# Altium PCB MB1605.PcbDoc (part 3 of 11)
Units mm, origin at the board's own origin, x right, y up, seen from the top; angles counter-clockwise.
Board outline 100 x 79.6 mm, 6 copper layers (Top Layer, Signal Layer 1, Signal Layer 2, Signal Layer 3, Signal Layer 4, Bottom Layer), stack 1.549 mm thick; 644 components, 529 nets, 2853 pads, 1462 vias.
Unrouted connection lines stored in the file: 2.
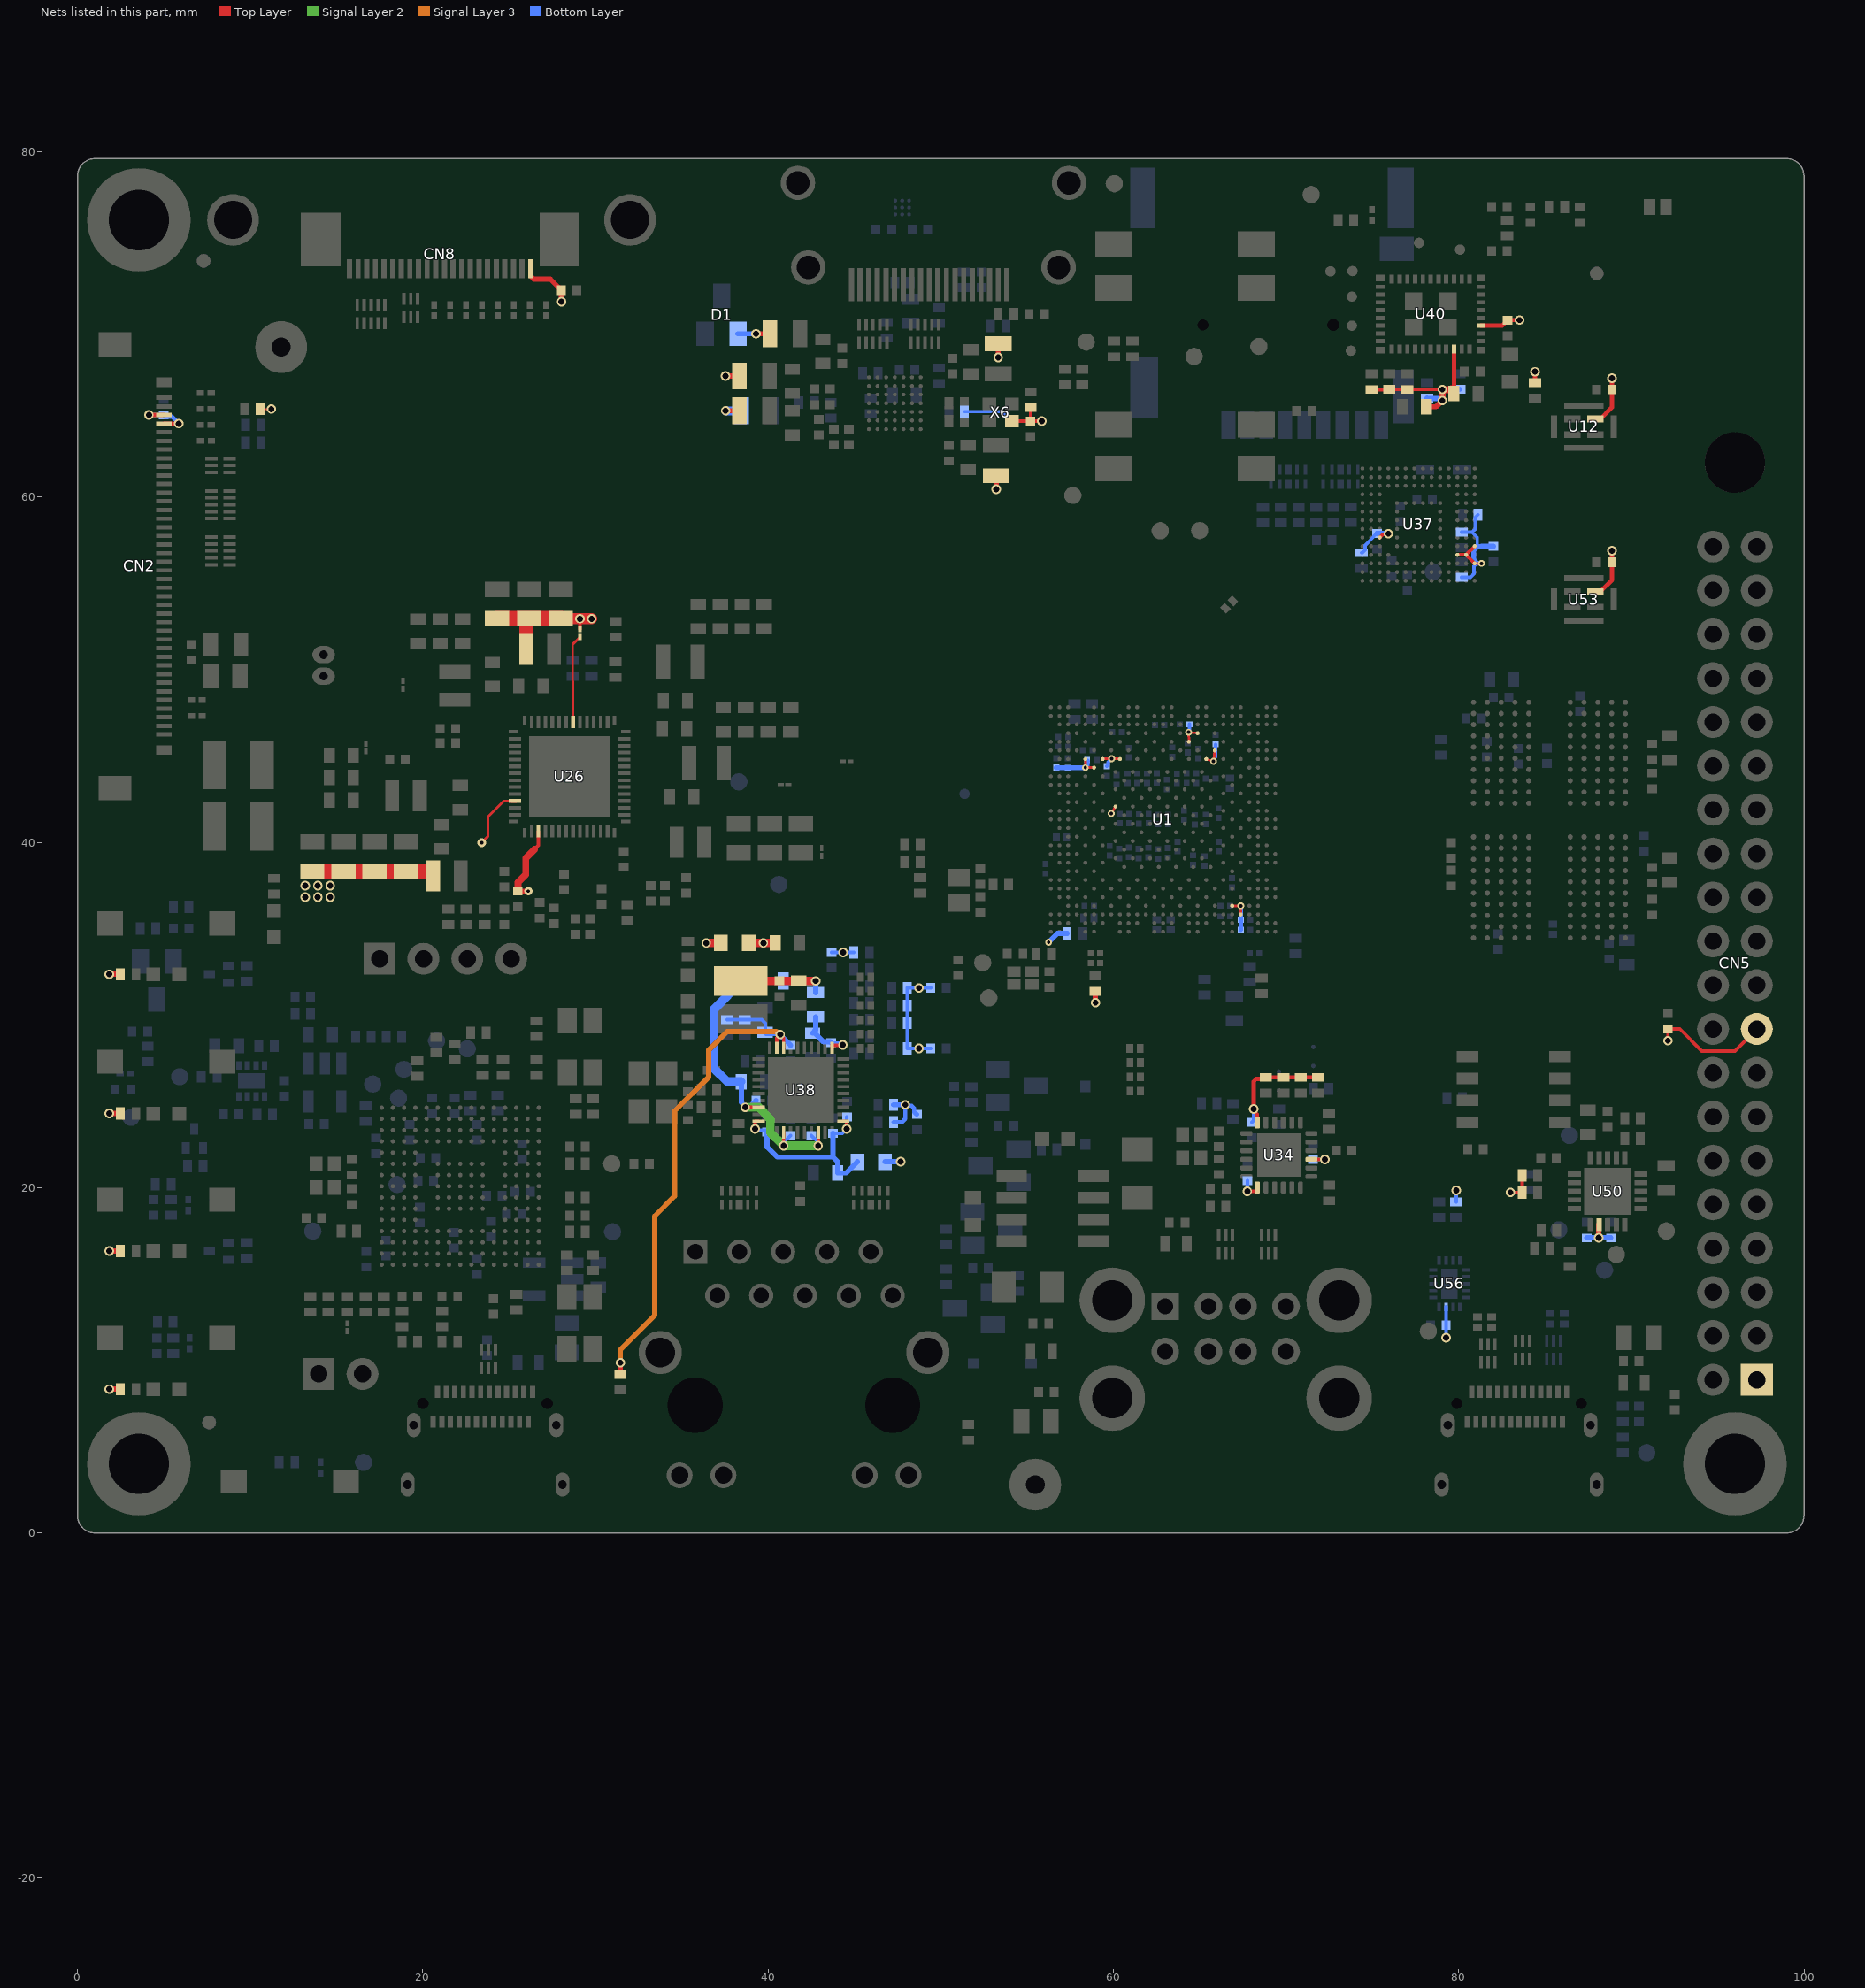
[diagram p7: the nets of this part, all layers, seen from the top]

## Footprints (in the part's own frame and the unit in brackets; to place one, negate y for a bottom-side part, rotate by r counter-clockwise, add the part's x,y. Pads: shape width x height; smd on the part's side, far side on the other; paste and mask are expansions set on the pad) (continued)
MIC_HCLGA_3X4X1_4LD [mm] "MCD-01715"
  rect 0.4x0.95 smd paste+0 mask+0.05: 1(0.45,-1.175) 2(0.45,0.175) 3(-0.45,0.175) 4(-0.45,-1.175)
  rect 0.35x2.3 smd paste+0 mask+0.05: 5(-1.225,-0.5) 5(1.225,-0.5)
  rect 1.3x0.35 smd paste+0 mask+0.05: 5(0,1.225) 5(0,-2.225)
  silkscreen extent -1.55,-2.55 1.55,1.55, body extent -1.45,-2.45 1.45,1.45, height 1.03
MIRE_PLACE_SMD_0P8MM [mm]
  round 0.8 smd paste-10 mask+0.2: 1(0,0)
  Top Layer keep-out circle w0.01: c0,0 r0.804
MOD_WLAN-BT_MURATA_LBEE5KL1YN-814 [mm]
  rect 0.25x0.5 smd mask+0.05: 1(-2.25,-2.025) 2(-1.8,-2.025) 3(-1.35,-2.025) 4(-0.9,-2.025) 5(-0.45,-2.025) 6(0,-2.025) 7(0.45,-2.025) 8(0.9,-2.025) 9(1.35,-2.025) 10(1.8,-2.025) 11(2.25,-2.025) 22(2.25,2.025) 23(1.8,2.025) 24(1.35,2.025) 25(0.9,2.025) 26(0.45,2.025) 27(0,2.025) 28(-0.45,2.025) 29(-0.9,2.025) 30(-1.35,2.025) 31(-1.8,2.025) 32(-2.25,2.025)
  rect 0.5x0.375 smd mask+0.05: 12(2.925,-2.087) 21(2.925,2.087) 33(-2.925,2.087) 42(-2.925,-2.087)
  rect 0.5x0.25 smd mask+0.05: 13(2.925,-1.575) 14(2.925,-1.125) 15(2.925,-0.675) 16(2.925,-0.225) 17(2.925,0.225) 18(2.925,0.675) 19(2.925,1.125) 20(2.925,1.575) 34(-2.925,1.575) 35(-2.925,1.125) 36(-2.925,0.675) 37(-2.925,0.225) 38(-2.925,-0.225) 39(-2.925,-0.675) 40(-2.925,-1.125) 41(-2.925,-1.575)
  rect 1x1 smd mask+0.05: 43(-1,-0.75) 44(1,-0.75) 45(-1,0.75) 46(1,0.75)
  silkscreen extent -3.57,-2.68 3.57,2.68, body extent -3.57,-2.68 3.57,2.68, height 1.11
MOS_SC89-3L [mm] "MCD-02221"
  rect 0.46x0.65 smd mask+0.05: 1(-0.5,-0.55) 2(0.5,-0.55) 3(0,0.55)
  silkscreen extent -0.85,-0.48 0.85,0.48, body extent -0.85,-0.85 0.85,0.85, height 0.85
MOS_SOT23 [mm]
  rect 1x1.4 smd mask+0.05: 1(-0.95,-1.1) 2(0.95,-1.1) 3(0,1.1)
  silkscreen extent -1.63,-0.82 1.63,0.82, body extent -1.56,-1.25 1.56,1.25, height 1.1
MOS_SOT23-5L [mm]
  rect 0.6x1.3 smd mask+0.05: 1(-0.95,-1.1) 2(0,-1.1) 3(0.95,-1.1) 4(0.95,1.1) 5(-0.95,1.1)
  silkscreen extent -1.6,-0.95 1.6,0.97, body extent -1.52,-1.25 1.52,1.25, height 1.45
PowerFLAT_5x6 [mm] "MCD-02152"
  rect 0.65x1.25 smd mask+0.05: 1(1.905,2.675) 2(0.635,2.675) 3(-0.635,2.675) 4(-1.905,2.675) 5(-1.905,-2.675) 6(-0.635,-2.675) 7(0.635,-2.675) 8(1.905,-2.675)
  Top Layer region: 0.2,-3.3 0.95,-3.3 0.95,-2.75 1.575,-2.75 1.575,-3.3 2.3,-3.3 2.3,-2.3 2.7,-2.3 2.7,-1.5 2.3,-1.5 2.3,0.15 2.7,0.15 2.7,0.975 2.3,0.975 2.3,1.15 0.2,1.15
  Top Layer region: -0.2,-3.3 -0.95,-3.3 -0.95,-2.75 -1.575,-2.75 -1.575,-3.3 -2.3,-3.3 -2.3,-2.3 -2.7,-2.3 -2.7,-1.5 -2.3,-1.5 -2.3,0.15 -2.7,0.15 -2.7,0.975 -2.3,0.975 -2.3,1.15 -0.2,1.15
  silkscreen extent -2.5,-3 2.5,3, body extent -2.6,-3.08 2.6,3.07, height 1
R0201_H0P23 [mm] "MCD-00702"
  rect 0.4x0.5 smd mask+0.05: 1(-0.3,0) 2(0.3,0)
  body extent -0.32,-0.17 0.32,0.17, height 0.26
R0402 [mm]
  rect 0.51x0.7 smd mask+0.05: 1(-0.45,0) 2(0.45,0)
  body extent -0.52,-0.3 0.52,0.3, height 0.4
R0603 [mm]
  rect 0.64x1 smd mask+0.05: 1(-0.7,0) 2(0.7,0)
  silkscreen extent -1.05,-0.58 1.05,0.58, body extent -0.9,-0.5 0.9,0.5, height 0.56
R0805 [mm]
  rect 0.85x1.3 smd mask+0.05: 1(-0.875,0) 2(0.875,0)
  silkscreen extent -0.33,-0.67 0.33,0.67, body extent -1.05,-0.68 1.05,0.68, height 0.65
Sheetbox_6L2S [mil] "Sheetbox 6 layers / 2 silkscreens"
  round 20 on Mech16: 1(813.5,208.05) 1(2736.63,208.05)
SOLDER-BRIDGE_R0603-0R [mil]
  round 10 smd paste-393.7: 1(-19.68,0) 2(23.62,0)
  Top Layer region: -47.24,-19.69 -47.24,19.68 -15.75,19.68 3.94,0 -15.75,-19.69 -47.24,-19.69
  Top Layer region: -5.91,19.68 13.78,0 -5.91,-19.69 47.24,-19.69 47.24,19.68 -5.91,19.68
  silkscreen extent -50,-23 50,23, body extent -36,-20 36,20, height 22
SWI_C&K_SDA02H1SBD_2POS [mm]
  rect 1.5x2.15 smd mask+0.05: 1(-1.27,-4.125) 2(1.27,-4.125) 3(1.27,4.125) 4(-1.27,4.125)
  silkscreen extent -3.55,-3.75 3.55,3.75, body extent -3.53,-4.65 3.53,4.65, height 5.45
SWI_WE_4341x10258x6 [mm]
  rect 1.5x1.4 smd: 1(-3.25,0) 2(3.25,0)
  silkscreen extent -3,-1.95 3,1.95, body extent -3.65,-1.95 3.65,1.95, height 2.5
SWI_WE_434121025816 [mm] "MCD-03492"
  rect 1.5x1.4 smd: 1(-3.25,0) 2(3.25,0)
  silkscreen extent -3,-1.95 3,1.95, body extent -3.65,-1.95 3.65,1.95, height 2.51
TP_PTH-1P02MM_TEST-TERMINAL_RS_101-2391_BLACK [mm] "MCD-00713"
  round 3 hole 1.1 mask+0.05: 1(0,0)
  silkscreen extent -1.62,-1.63 1.62,1.63, body extent -1.24,-1.25 1.25,1.25, height 4.85
TP_SMD_0-6MM [mm]
  round 0.6 smd paste-10 mask+0.05: 1(0,0)
  silkscreen extent -0.5,-0.5 0.5,0.5
TP_SMD_1MM [mm]
  round 1 smd paste-10 mask+0.05: 1(0,0)
  silkscreen extent -0.7,-0.7 0.7,0.7

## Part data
B1 B2 B3: library part MCD-03492, "Switch tactile, SPST-NO, 50mA, 12V, 6x3.8mm", Manufacturer="WURTH ELEKTRONIC", Manufacturer_Part_Number=434121025816, Package=6x3.8mm
B4 B5: library part MCD-03491, "Switch tactile, SPST-NO, 50mA, 12V, 6x3.8mm", Manufacturer="WURTH ELEKTRONIC", Manufacturer_Part_Number=434111025826, Package=6x3.8mm
C1 C90 C92 C119: library part MCD-00674, "Capacitor, MLCC, 6.8pF, 50V, NPO, +-0.25pF, 0402, T=0.5mm", Alternate_Manufacturer=N/A, Manufacturer=YAGEO, Manufacturer_Part_Number=CC0402CRNPO9BN6R8, Package=0402
C2 C3 C10 C11: library part MCD-01341, "Capacitor, MLCC, 10uF, 6V3, X5R, 20%, 0603, T=0,8mm", Alternate_Manufacturer=MURATA, Alternate_Manufacturer_Part_Number=GRM188R60J106ME84D, Manufacturer_Part_Number=GRM188R60J106ME47D, Package=0603
C4 C5 C6 C7 C8 C12 C13 C14 C15 C16 C17 C18 C19 C20 C21 C31 C101 C102 C105 C106 C107 C108 C113 C122 C125 C139 C146 C149 C155 C177 C180 C181 C182 C227 C232 C233 C281 C282 C289 C290 C297 C298 C299 C303 C310 C311 C324 C325 C326 C327 C328 C329 C333 C334: library part MCD-00006, "Capacitor, MLCC, 100nF, 16V, X7R, +/-10%, 0402, T=0.5mm", Manufacturer=YAGEO, Manufacturer_Part_Number=CC0402KRX7R7BB104, Package=0402
C9 C89 C114 C115 C116 C118 C126 C127 C130 C161 C162: library part MCD-00006, "Capacitor, MLCC, 100nF, 16V, X7R, +/-10%, 0402, T=0.5mm", Alternate_Manufacturer=MURATA, Alternate_Manufacturer_Part_Number=GCM155R71C104KA55D, Manufacturer=YAGEO, Manufacturer_Part_Number=CC0402KRX7R7BB104, Package=0402
C22 C23 C24 C26 C27 C28 C34 C35 C36 C37 C41 C183 C200 C202: library part MCD-00100, "Capacitor, MLCC, 22uF, 6V3, X5R, +/-20%, 0603, T=0,8mm", Alternate_Manufacturer=N/A, Manufacturer=MURATA, Manufacturer_Part_Number=GRM188R60J226MEA0J, Package=0603
C25 C157 C158 C173 C219: library part MCD-02198, "Capacitor, MLCC, 10nF, 50V, X7R, +/-10%, 0402, T=0.5mm", Manufacturer=YAGEO, Manufacturer_Part_Number=CC0402KRX7R9BB103, Package=0402
C29 C30 C32 C38 C56 C184 C199: library part MCD-00099, "Capacitor, MLCC, 10uF, 10V, X5R, +/-10%, 0603, T=0,8mm", Alternate_Manufacturer=N/A, Manufacturer=MURATA, Manufacturer_Part_Number=GRM188R61A106KE69D, Package=0603
C33: library part MCD-00011, "Capacitor, MLCC, 10nF, 16V, X7R, 10%, 0402, T=0.5mm", Manufacturer=YAGEO, Manufacturer_Part_Number=CC0402KRX7R7BB103, Package=C0402
C39 C43 C188 C213 C216: library part MCD-00095, "Capacitor, MLCC, 1uF, 25V, X5R, +/-10%, 0402, T=0.5mm", Manufacturer=MURATA, Manufacturer_Part_Number=GRM155R61E105KA12, Package=0402
C40: library part MCD-03140, "Capacitor, MLCC, 10uF, 6.3V, X5R, +/-20%, 0402, T=0.5mm", Manufacturer=MURATA, Manufacturer_Part_Number=GRM155R60J106ME05D, Package=0402
C42 C147: library part MCD-01796, "Capacitor, Tantalum, 100uF, 6V3, 40mR, +/-20%,  Type_B (3528 metric), T=1.9mm", Manufacturer=AVX, Manufacturer_Part_Number=TCJB107M006R0040, Package="3528 (metric)"
C44 C45 C46 C47 C48 C49 C50 C51 C52 C53 C54 C55 C57 C58 C59 C60 C62 C63 C64 C65 C66 C67 C68 C69 C70 C71 C72 C73 C74 C75 C76 C77 C82 C83: library part MCD-02377, "Capacitor, MLCC, 1uF, 6.3V, X5R, +/-20%, 0201, T=0,3mm", Manufacturer=MURATA, Manufacturer_Part_Number=GRM033R60J105MEA2, Package=0201
C61 C91 C179 C189 C190 C208 C209 C214 C215 C217 C335: library part MCD-01356, "Capacitor, MLCC, 4.7uF, 6V3, X5R, +/-20%, 0402, T=0.5mm", Manufacturer=MURATA, Manufacturer_Part_Number=GRM155R60J475ME47, Package=0402
C78 C79 C80 C96 C97 C98: library part MCD-00100, "Capacitor, MLCC, 22uF, 6V3, X5R, +/-20%, 0603, T=0.8mm", Manufacturer=MURATA, Manufacturer_Part_Number=GRM188R60J226MEA0J, Package=0603
C81 C86: library part MCD-01775, "Capacitor, MLCC, 3.3pF, 50V, NPO, +/-0.1pF, 0402, T=0.5mm", Manufacturer=YAGEO, Manufacturer_Part_Number=CC0402BRNPO9BN3R3, Package=0402
C84 C93: library part MCD-02352, "Capacitor, MLCC, 100nF, 10V, X5R, +/-10%, 0402, T=0,5mm", Manufacturer=YAGEO, Manufacturer_Part_Number=CC0402KRX5R6BB104, Package=0402
C85 C143: library part MCD-00204, "Capacitor, MLCC, 47uF, 10V, X5R, +/-20%, 0805, T=1.25mm", Manufacturer=MURATA, Manufacturer_Part_Number=GRM21BR61A476ME15K, Package=0805
C87 C103 C104 C109 C123 C137 C141 C152 C228 C229 C295 C296 C306 C309 C314 C317 C322 C323: library part MCD-00006, "Capacitor,100nF,16V,X7R,10%,0402", Alternate_Manufacturer=MURATA, Alternate_Manufacturer_Part_Number=GCM155R71C104KA55D, Manufacturer=YAGEO, Manufacturer_Part_Number=CC0402KRX7R7BB104, Package=0402
C88: library part MCD-01823, "Capacitor, MLCC, 2.2uF, 6V3, X5R,+/-10%, 0402, T=0.5mm", Alternate_Manufacturer=N/A, Manufacturer=MURATA, Manufacturer_Part_Number=GRM155R60J225KE95D, Package=0402
C94: library part MCD-01995, "Capacitor, MLCC, 22pF, 50V, C0G, +/-5%, 0402, T=0.5mm", Manufacturer=TDK, Manufacturer_Part_Number=C1005NP01H220J050BA, Package=0402
C95 C163 C212: library part MCD-00198, "Capacitor, MLCC, 1nF, 16V, X7R, +/-10%, 0402, T=0.5mm", Manufacturer=YAGEO, Manufacturer_Part_Number=CC0402KRX7R7BB102, Package=0402
C99: library part MCD-00011, "Capacitor, MLCC, 10nF, 16V, X7R, 10%, 0402, T=0.5mm", Alternate_Manufacturer=N/A, Manufacturer=YAGEO, Manufacturer_Part_Number=CC0402KRX7R7BB103, Package=0402
C100 C265 C266 C267: library part MCD-00697, "Capacitor, MLCC, 100nF,10V, X5R, +/-10%, 0201, T=0.3mm", Alternate_Manufacturer=N/A, Manufacturer=TDK, Manufacturer_Part_Number=C0603X5R1A104K030BC, Package=0201
C110 C159: library part MCD-02372, "Capacitor, MLCC, 2.2uF, 25V, X7R, +/-10%, 0805, T=1,25mm", Manufacturer=MURATA, Manufacturer_Part_Number=GRM21BR71E225KE11L, Package=0805
C111 C120 C280 C288 C302 C332: library part MCD-00100, "Capacitor,22uF,6V3,X5R,20%,0603", Manufacturer=MURATA, Manufacturer_Part_Number=GRM188R60J226MEA0J, Package=0603
C117 C128 C132 C145 C148 C160: library part MCD-02606, "Capacitor, MLCC, 2.2uF, 6.3V, X5R, +/-10%, 0402, T=0.5mm", Manufacturer=YAGEO, Manufacturer_Part_Number=CC0402KRX5R5BB225, Package=0402
C129 C165 C169: library part MCD-00099, "Capacitor, MLCC, 10uF, 10V, X5R, +/-10%, 0603, T=0.8mm", Manufacturer=MURATA, Manufacturer_Part_Number=GRM188R61A106KE69D, Package=0603
C131: library part MCD-00016, "Capacitor, MLCC, 20pF, 50V, NPO, +/- 5%, 0402, T=0.5mm", Manufacturer=YAGEO, Manufacturer_Part_Number=CC0402JRNPO9BN200, Package=0402
C133 C140: library part MCD-01374, "Capacitor, MLCC, 5.6pF, 50V, NPO, +/-0.1pF, 0402, T=0.5mm", Manufacturer=YAGEO, Manufacturer_Part_Number=CC0402BRNPO9BN5R6, Package=0402
C134 C218: library part MCD-01356, "Capacitor, MLCC, 4.7uF, 6V3, X5R, 20%, 0402, T=0,5mm", Alternate_Manufacturer=MURATA, Alternate_Manufacturer_Part_Number=GRM155R60J475ME87, Manufacturer_Part_Number=GRM155R60J475ME47, Package=0402
C135: library part MCD-00099, "Capacitor, MLCC, 10uF, 10V, X5R, 10%, 0603, T=0,8mm", Manufacturer=MURATA, Manufacturer_Part_Number=GRM188R61A106KE69D, Package=0603
C136: library part MCD-00012, "Capacitor, MLCC, 2.2uF, 10V, X5R, 10%, 0603, T=0,8mm", Alternate_Manufacturer=KEMET, Alternate_Manufacturer_Part_Number=C0603C225K8PACTU, Manufacturer=YAGEO, Manufacturer_Part_Number=CC0603KRX5R6BB225, Package=0603
C150 C226: library part MCD-00104, "Capacitor, MLCC, 220uF, 6V3, X5R, +/-20%, 1206, T=1.6mm", Manufacturer=MURATA, Manufacturer_Part_Number=GRM31CR60J227ME11, Package=1206
C151 C250 C252 C260: library part MCD-02377, "Capacitor, MLCC, 1uF, 6.3V, X5R, +/-20%, 0201, T=0,3mm", Alternate_Manufacturer=N/A, Manufacturer=MURATA, Manufacturer_Part_Number=GRM033R60J105MEA2, Package=0201
C156 C164: library part MCD-00205, "Capacitor, MLCC, 100pF, 50V, NPO, +/-5%, 0402, T=0.5mm", Manufacturer=YAGEO, Manufacturer_Part_Number=CC0402JRNPO9BN101, Package=0402
C166 C172: library part MCD-02355, "Capacitor, MLCC, 100nF, 25V, X7R, +/-10%, 0402, T=0.5mm", Manufacturer=WALSIN, Manufacturer_Part_Number=0402B104K250CT, Package=0402
C167 C174 C175 C176: library part MCD-00200, "Capacitor, MLCC, 12pF, 50V, NPO, 5%, 0402, T=0,5mm", Alternate_Manufacturer=N/A, Manufacturer=YAGEO, Manufacturer_Part_Number=CC0402JRNPO9BN120, Package=0402
C168 C171: library part MCD-00724, "Capacitor, MLCC, 470pF, 50V, NPO, +/-5%, 0402, T=0.5mm", Manufacturer=YAGEO, Manufacturer_Part_Number=CC0402JRNPO9BN471, Package=0402
C170: library part MCD-01099, "Capacitor, MLCC, 100nF, 50V, X7R, +/-10%, 0603, T=0.8mm", Manufacturer=YAGEO, Manufacturer_Part_Number=CC0603KRX7R9BB104, Package=0603
C185 C186 C187 C193 C194 C198 C203 C204 C206 C207: library part MCD-03139, "Capacitor, MLCC, 22uF, 10V, X5R, +/-20%, 0805, T=1,25mm", Manufacturer=MURATA, Manufacturer_Part_Number=GRM21BR61A226ME51L, Package=0805
C192 C195 C196 C197 C201 C205 C220 C234 C236 C237 C238 C239 C240 C244 C246 C248 C251 C253: library part MCD-01535, "Capacitor, MLCC,100nF, 10V, X7R, +/-10%, 0201, T=0.3mm", Alternate_Manufacturer=N/A, Manufacturer=MURATA, Manufacturer_Part_Number=GRM033R61A104KE15, Package=0201
C222 C223: library part MCD-00015, "Capacitor,10pF,50V,NPO,5%,0402", Manufacturer=YAGEO, Manufacturer_Part_Number=CC0402JRNPO9BN100, Package=0402
C224: library part MCD-00095, "Capacitor, MLCC, 1uF, 25V, X5R, +/-10%, 0402, T=0,5mm", Alternate_Manufacturer=MURATA, Alternate_Manufacturer_Part_Number=GRM155R60J105KE19, Manufacturer_Part_Number=GRM155R61E105KA12, Package=0402
C225: library part MCD-01534, "Capacitor, MLCC, 4,7uF, 6V3, X5R, +/-20%, 0201, T=0.5mm", Alternate_Manufacturer=N/A, Manufacturer=MURATA, Manufacturer_Part_Number=GRM035R60J475ME15, Package=0201
C235: library part MCD-02235, "Capacitor, MLCC, 2.2uF, 10V, X5R,+/-10%, 0201, T=0.5mm", Manufacturer=MURATA, Manufacturer_Part_Number=GRM033R61A225KE47D, Package=0201
CN1: library part MCD-00307, "HDMI_Type A, Receptacle, 19x1, 0.5mm, VR, SMD, T= 6.1mm", Manufacturer="AMPHENOL ICC", Manufacturer_Part_Number=10029449-001RLF
CN2: library part MCD-03562, "Socket_FFC/FPC, 40pins, 0.5mm, RA, SMD, T=1mm", Manufacturer=I-PEX, Manufacturer_Part_Number=20455-040E-76
CN5: library part MCD-00302, "Header, 20x2, 2.54mm, VR, TH, T=5.84mm/2.54mm", Manufacturer=SAMTEC, Manufacturer_Part_Number=TSW-120-07-G-D
CN6: library part MCD-00023, "MicroSD Card Conn, Reversed-Type, Mnt Push-Push, Positionning holes", Alternate_Manufacturer=N/A, Manufacturer=YAMAICHI, Manufacturer_Part_Number=PJS008-2003-1
CN8: library part MCD-03600, "Socket_FFC/FPC, 22pins, 0.5mm, RA, SMD, T=2mm", Manufacturer="TE CONNECTIVITY"
CN12: library part MCD-00655, "Header 2 circuits, 1.25mm Pitch ,  Vertical, with Friction Lock", Alternate_Manufacturer=N/A, Manufacturer=MOLEX, Manufacturer_Part_Number=53047-0210
CN14: library part MCD-00029, "Header, 4x1, 2.54mm, VR, TH, T=5.84mm/2.54mm", Manufacturer=SAMTEC, Manufacturer_Part_Number=TSW-104-07-G-S
CN15 CN21: library part MCD-03232, "USB_TypeC, 24 pins, RA, SMD, T=2.96mm (USB Certified 3.1)", Manufacturer="AMPHENOL ICC", Manufacturer_Part_Number=12401826E412A
CN16: library part MCD-01129, "Connector_RJ45, led pull down, T= 13.84mm", Manufacturer="YUAN DEAN SCIENTIFIC", Manufacturer_Part_Number=48F-01GYDXNL, Package=13.84x21.59mm
CN19: library part MCD-00109, "USB_Dual-TypeA, Receptacle, 8pins, 2.5mm, RA, TH, T= 15.5mm", Manufacturer=CONEXCON, Manufacturer_Part_Number=5600-3081
D1: library part MCD-02333, "Diode, Ultrafast and RF switching diode, VF=0.41V@IF=1mA, VBR=70V", Manufacturer=STMICROELECTRONICS, Manufacturer_Part_Number=BAR18FILM, Package=SOT-23
D2 D5: library part MCD-03688, "Diode, Schottky, 0V33, 0.5A , 30V, SOD123", Manufacturer=STMICROELECTRONICS, Manufacturer_Part_Number=STPS0530Z, Package=SOD123
D6: library part MCD-03280, "Diode, Schottky, Dual Common Cathode, 0V3, 300mA, 40V, SOT-23", Manufacturer=STMICROELECTRONICS, Manufacturer_Part_Number=BAT54CFILM, Package=SOT-23
D7: library part MCD-00034, Manufacturer=STMICROELECTRONICS, Manufacturer_HQ_COO=EU
JP3: library part MCD-00045, "Header, 2x1, 2.54mm, VR, TH, T=5.84mm/2.54mm", Manufacturer=SAMTEC, Manufacturer_Part_Number=TSW-102-07-G-S
L1 L6: library part MCD-03143, "Inductor, 2.2uH, +/-20%, Itemp= 1700mA, Isat= 2400mA, 0R140, 0806, T=1mm", Manufacturer=MURATA, Manufacturer_Part_Number=DFE201610E-2R2M{}P2, Package=0806
L2 L4: library part MCD-03142, "Inductor, 0.68uH, +/-20%, Itemp= 3900mA, Isat= 5400mA, 0R031, 1008, T=1.2mm", Manufacturer=MURATA, Manufacturer_Part_Number=DFE252012F-R68M{}P2, Package=1008
L3 L5 L7: library part MCD-03141, "Inductor, 0.68uH, +/-20%, Itemp= 3100mA, Isat= 4300mA, 0R043, 0806, T=1mm", Manufacturer=MURATA, Manufacturer_Part_Number=DFE201610E-R68M{}P2, Package=0806
L9: library part MCD-00657, "Inductor,2.4nH,+-0.2nH,0.05R,0.85A,0402", Manufacturer=MURATA, Manufacturer_Part_Number=LQW15AN2N4C00#, Package=0402
L10: library part MCD-00659, "Inductor, 2.2µH, 20%, Isat 0.35A, DCR 0.2Ohm, 0603", Manufacturer=MURATA, Manufacturer_Part_Number=LQM18PN2R2MGH, Package=0603
L11 L13 L16 L17 L18 L19: library part MCD-02317, "Inductor, 10uH, +/-20%, Isat 100mA, DCR 0.5Ohm,", Alternate_Manufacturer=TDK, Alternate_Manufacturer_Part_Number=MLZ2012M100WT000, Manufacturer=MURATA, Manufacturer_Part_Number=LQM21FN100M80L, Package=0805
L12: library part MCD-00305, "Ferrite bead, 26R @ 100Mhz, +/-25%, 6000mA, 0R007, 0603, T=0.75mm", Manufacturer=MURATA, Manufacturer_Part_Number=BLM18KG260TN1, Package=0603
L15 L21: library part MCD-00094, "Ferrite bead 100R 2A 0603", Manufacturer=MURATA, Manufacturer_Part_Number=BLM18EG101TN1, Package=0603
LD2 LD8 LD11: library part MCD-00588, "LED Green, 0603 SMD, Forward Voltage Typ=2V, Max=2.5V", Alternate_Manufacturer="VISHAY SEMICONDUCTOR OPTO DIVISION", Alternate_Manufacturer_Part_Number=VLMTG1300-GS08, Manufacturer="OSRAM OPTO SEMICONDUCTORS", Manufacturer_Part_Number="LG Q396-PS-35", Package="LED 0603"
LD4 LD7: library part MCD-00587, "LED Red, 0603 SMD, 2V Forward Voltage", Alternate_Manufacturer="OSRAM OPTO SEMICONDUCTORS", Alternate_Manufacturer_Part_Number="LS Q976-NR-1", Manufacturer=VISHAY, Manufacturer_Part_Number=VLMS1300-GS08, Package="LED 0603"
LD5 LD6: library part MCD-02631, "LED Bicolor, Green/Red, 2V, 20mA,  4-PLCC", Manufacturer="WURTH ELEKTRONIK", Manufacturer_Part_Number=150141SV73110, Package=4-PLCC
LD9: library part MCD-00590, "LED Orange, 0603 SMD, Forward Voltage Min=1.6V, Max=2.4V", Alternate_Manufacturer="VISHAY SEMICONDUCTOR OPTO DIVISION", Alternate_Manufacturer_Part_Number=VLMO1300-GS08, Manufacturer="OSRAM OPTO SEMICONDUCTORS", Manufacturer_Part_Number="LO Q976-PS-25", Package="LED 0603"
LE1: library part MCD-00048, "FIXED IND 4.7UH 1A 180 MOHM 30% SMD", Manufacturer=MURATA, Manufacturer_Part_Number=LQH32PN4R7NN0L, Package=1210
LED1: library part MCD-00585, "LED Blue, 0603 SMD, Forward Voltage Min=2,8V, Max=3,8V", Alternate_Manufacturer=EVERLIGHT, Alternate_Manufacturer_Part_Number=19-217-BHC-ZL1M2RY-3T-V4, Manufacturer="OSRAM OPTO SEMICONDUCTORS", Manufacturer_Part_Number="LB Q39G-L2OO-35-1", Package="LED 0603"
LNK1 LNK2 LNK4 LNK7 LNK8 LNK11: library part MCD-02777, "Track link on PCB 200um width for layout routing", Manufacturer=N/A
LNK13: library part MCD-02777, "Track link on PCB 200um width for layout routing. No component assembly and no component in BOM", Manufacturer=N/A
Q1 Q2 Q3: library part MCD-02221, "MOSFET N-CH 20V SC-89", Alternate_Manufacturer=N/A, Manufacturer=VISHAY, Manufacturer_Part_Number=Si1062X, Package=SC-89
Q5: library part MCD-02152, "MOSFET, Dual N-channel 30 V, 0.016 Ω typ., 40 A, STripFET™ H5 Power MOSFET", Manufacturer=STMICROELECTRONICS, Manufacturer_HQ_COO=EU, Package="PowerFLAT 5x6"
Q9 Q10: library part MCD-03690, "Transistor, MOSFET, P-CH, 30V, 3.8A, SOT23", Manufacturer="DIODES INCORPORATED", Manufacturer_Part_Number=DMP3099L, Package=SOT23
Q11 Q12: library part MCD-03691, "Transistor, MOSFET, N-CH, 30V, 0.9A, SOT23", Manufacturer="DIODES INCORPORATED", Manufacturer_Part_Number=DMN3731U
R1 R2: library part MCD-02253, "Resistor, 240R, 0201, +/-1%, 1/20W", Alternate_Manufacturer=N/A, Manufacturer=YAGEO, Manufacturer_Part_Number=RC0201FR-07240RL, Package=0201
R3 R15 R16 R17 R76 R156 R213 R214 R215 R220 R223 R323 R324: library part MCD-00053, "Resistor, 10K, 0402, +/-1%, 1/16W", Manufacturer=YAGEO, Manufacturer_Part_Number=RC0402FR-0710KL, Package=0402
R4: library part MCD-00179, "Resistor, 0R, 0805, +/-5%, 1/8W", Manufacturer=YAGEO, Manufacturer_Part_Number=RC0805JR-070RL, Package=0805
R5 R6 R7 R250 R251: library part MCD-00417, "Resistor, 200R, 0402, +/-1%, 1/16W", Manufacturer=YAGEO, Manufacturer_Part_Number=RC0402FR-07200RL, Package=0402
R8 R12 R219: library part MCD-02335, "Resistor, 140K, 0402, +/-1%, 1/16W", Manufacturer=YAGEO, Manufacturer_Part_Number=RC0402FR-07140KL, Package=0402
R9 R120 R121 R147 R148 R149 R150 R161 R164 R167 R173 R176 R178 R185 R196: library part MCD-02978, "Resistor, 22R, 0201, +/-1%, 1/20W", Manufacturer=YAGEO, Manufacturer_Part_Number=RC0201FR-0722RL, Package=0201
R10 R40 R46 R57 R59 R60 R61 R64 R75 R81 R267 R269 R286: library part MCD-00052, "Resistor,0R,0402,5%,1/16W", Alternate_Manufacturer=N/A, Manufacturer=YAGEO, Manufacturer_Part_Number=RC0402JR-070RL, Package=0402
R11: library part MCD-00056, "Resistor, 0R, 0603, +/-5%, 1/10W", Manufacturer=YAGEO, Manufacturer_Part_Number=RC0603JR-070RL, Package=0603
R13 R21 R22 R25: library part MCD-00419, "Resistor, 2K, 0402, +/-1%, 1/16W", Manufacturer=YAGEO, Manufacturer_Part_Number=RC0402FR-072KL, Package=0402
R18 R139: library part MCD-00061, "Resistor, 1K, 0402, +/-1%,1/16W", Manufacturer=YAGEO, Manufacturer_Part_Number=RC0402FR-071KL, Package=0402
R20 R23 R24 R26 R29 R30 R63 R67 R129 R154 R155 R211 R212: library part MCD-00052, "Resistor, 0R, 0402, +/-5%, 1/16W", Manufacturer=YAGEO, Manufacturer_Part_Number=RC0402JR-070RL, Package=0402
R27 R33 R34 R52 R100 R107 R125 R205 R272: library part MCD-00053, "Resistor,10K,0402,1%,1/16W", Alternate_Manufacturer=N/A, Manufacturer=YAGEO, Manufacturer_Part_Number=RC0402FR-0710KL, Package=0402
R28: library part MCD-00444, "Resistor, 27K, 0603, +/-1%, 1/10W", Manufacturer=YAGEO, Manufacturer_Part_Number=RC0603FR-0727KL, Package=0603
R31 R32 R224 R228 R245 R246: library part MCD-00068, "Resistor,1K5,0402,1%,1/16W", Alternate_Manufacturer=N/A, Manufacturer=YAGEO, Manufacturer_Part_Number=RC0402FR-071K5L, Package=0402
R35 R36 R37 R38 R39: library part MCD-00063, "Resistor,47K,0402,1%,1/16W", Alternate_Manufacturer=N/A, Manufacturer=YAGEO, Manufacturer_Part_Number=RC0402FR-0747KL, Package=0402
R41 R162 R187 R200 R217 R218 R227 R229 R239: library part MCD-00059, "Resistor, 100K, 0402, +/-1%, 1/16W", Manufacturer=YAGEO, Manufacturer_Part_Number=RC0402FR-07100KL, Package=0402
R42: library part MCD-00053, "Resistor, 10K, 0402, +/-1%, 1/16W", Alternate_Manufacturer=N/A, Manufacturer=YAGEO, Manufacturer_Part_Number=RC0402FR-0710KL, Package=0402
R44 R96 R122 R123 R124: library part MCD-00061, "Resistor,1K,0402,1%,1/16W", Alternate_Manufacturer=N/A, Manufacturer=YAGEO, Manufacturer_Part_Number=RC0402FR-071KL, Package=0402
R66: library part MCD-00058, "Resistor, 20R, 0402, +/-1%, 1/16W", Alternate_Manufacturer=N/A, Manufacturer=YAGEO, Manufacturer_Part_Number=RC0402FR-0720RL, Package=0402
R69 R101 R103 R104 R248: library part MCD-00053, "Resistor,10K,0402,1%,1/16W", Manufacturer=YAGEO, Manufacturer_Part_Number=RC0402FR-0710KL, Package=0402
R87 R88 R182 R188: library part MCD-00052, "Resistor,0R,0402,5%,1/16W", Manufacturer=YAGEO, Manufacturer_Part_Number=RC0402JR-070RL, Package=0402
R89 R90 R91 R92 R93: library part MCD-00063, "Resistor,47K,0402,1%,1/16W", Manufacturer=YAGEO, Manufacturer_Part_Number=RC0402FR-0747KL, Package=0402
R94 R95 R98 R99 R102 R105 R106 R128 R135 R137 R141 R143: library part MCD-00059, "Resistor,100K,0402,1%,1/16W", Alternate_Manufacturer=YAGEO, Alternate_Manufacturer_Part_Number=RT0402FRE07100KL, Manufacturer_Part_Number=RC0402FR-07100KL, Package=0402
R97: library part MCD-00187, "Resistor,12K,0402,1%,1/16W", Alternate_Manufacturer=N/A, Manufacturer=YAGEO, Manufacturer_Part_Number=RC0402FR-0712KL, Package=0402
R109 R110 R111 R112 R113 R114 R158 R292 R293 R303 R304 R305 R319 R322: library part MCD-00065, "Resistor,4K7,0402,1%,1/16W", Alternate_Manufacturer=YAGEO, Alternate_Manufacturer_Part_Number=RT0402FRE074K7L, Manufacturer_Part_Number=RC0402FR-074K7L, Package=0402
R126 R127: library part MCD-00062, "Resistor,330R,0402,1%,1/16W", Alternate_Manufacturer=N/A, Manufacturer=YAGEO, Manufacturer_Part_Number=RC0402FR-07330RL, Package=0402
R130 R132: library part MCD-00062, "Resistor, 330R, 0402, +/-1%, 1/16W", Manufacturer=YAGEO, Manufacturer_Part_Number=RC0402FR-07330RL, Package=0402
R131 R133: library part MCD-02665, "Resistor, 1K, 0402, +/-0.1%, 1/16W, +/-25ppm/°C", Manufacturer=YAGEO, Manufacturer_Part_Number=RT0402BRD071KL, Package=0402
R134 R153 R207 R209: library part MCD-00455, "Resistor, 33R, 0402, +/-1%, 1/16W", Manufacturer=YAGEO, Manufacturer_Part_Number=RC0402FR-0733RL, Package=0402
R136: library part MCD-00461, "Resistor,360R,0402,1%,1/16W", Manufacturer=YAGEO, Manufacturer_Part_Number=RC0402FR-07360RL, Package=0402
R138 R151 R210: library part MCD-00441, "Resistor,270R,0402,1%,1/16W", Manufacturer=YAGEO, Manufacturer_Part_Number=RC0402FR-07270RL, Package=0402
R140 R181: library part MCD-00067, "Resistor, 100R, 0402, +/- 1%, 1/16W", Manufacturer=YAGEO, Manufacturer_Part_Number=RC0402FR-07100RL, Package=0402
R142: library part MCD-00449, "Resistor,300R,0402,1%,1/16W", Manufacturer=YAGEO, Manufacturer_Part_Number=RC0402FR-07300RL, Package=0402
R144: library part MCD-00194, "Resistor,120R,0402,1%,1/16W", Manufacturer=YAGEO, Manufacturer_Part_Number=RC0402FR-07120RL, Package=0402
R191 R195 R260 R261 R318: library part MCD-00068, "Resistor,1K5,0402,1%,1/16W", Manufacturer=YAGEO, Manufacturer_Part_Number=RC0402FR-071K5L, Package=0402
R194 R230: library part MCD-00185, "Resistor, 3K, 0402, +/-1%, 1/16W", Manufacturer=YAGEO, Manufacturer_Part_Number=RC0402FR-073KL, Package=0402
R199: library part MCD-00183, "Resistor,2K49,0402,1%,1/16W", Manufacturer=YAGEO, Manufacturer_Part_Number=RC0402FR-072K49L, Package=0402
R216 R221 R222: library part MCD-00333, "Resistor, 5K1, 0402, +/-1%, 1/16W", Manufacturer=YAGEO, Manufacturer_Part_Number=RC0402FR-075K1L, Package=0402
R225: library part MCD-02232, "Resistor, 22mR, 0603, +/-1%, 1/3W", Manufacturer=PANASONIC, Manufacturer_Part_Number=ERJ-3BWFR022V, Package=0603
R226 R242: library part MCD-02455, "Resistor, 3K9, 0402, +/-1%, 1/16W, +/-100ppm/°C", Manufacturer=YAGEO, Manufacturer_Part_Number=RC0402FR-073K9L, Package=0402
R231: library part MCD-00435, "Resistor, 24K, 0402, +/-1%, 1/16W", Manufacturer=YAGEO, Manufacturer_Part_Number=RC0402FR-0724KL, Package=0402
R232 R327: library part MCD-02265, "Resistor,100K,0402,0.5%,1/16W", Manufacturer=YAGEO, Manufacturer_Part_Number=RC0402DR-07100KL, Package=0402
R233 R234: library part MCD-00064, "Resistor,510R,0402,1%,1/16W", Manufacturer=YAGEO, Manufacturer_Part_Number=RC0402FR-07510RL, Package=0402
R240: library part MCD-00381, "Resistor, 1K3, 0402, +/-1%, 1/16W", Manufacturer=YAGEO, Manufacturer_Part_Number=RC0402FR-071K3L, Package=0402
R241: library part MCD-00409, "Resistor, 1K8, 0402, +/-1%, 1/16W", Manufacturer=YAGEO, Manufacturer_Part_Number=RC0402FR-071K8L, Package=0402
R310 R313: library part MCD-00056, "Resistor,0R,0603,5%,1/10W", Manufacturer=YAGEO, Manufacturer_Part_Number=RC0603JR-070RL, Package=0603
R325: library part MCD-00182, "Resistor, 1M, 0402, +/-1%, 1/16W", Manufacturer=YAGEO, Manufacturer_Part_Number=RC0402FR-071ML, Package=0402
SB1 SB2: library part MCD-00071, "Solder Bridge ON", Manufacturer=YAGEO, Manufacturer_Part_Number=RC0603JR-070RL, Package=SB0603
SW1 SW2: library part MCD-00658, "Dip Switch ,2Position ,Surface Mount Slide (Standard) ,2.54 pitch,25mA 24VDC", Manufacturer=C&K, Manufacturer_Part_Number=SDA02H1SBD, Package=DIP
TP1 TP9 TP10 TP14 TP17 TP18 TP19 TP20: library part MCD-00631, "Test Point 0.6mm", Manufacturer=N/A
TP2 TP3 TP4 TP5 TP6 TP7 TP11 TP12 TP13 TP15 TP16 TP21 TP22 TP23 TP24 TP25 TP26 TP27 TP28 TP29 TP30 TP31 TP32 TP35 TP40 TP41 TP42 TP43 TP44: library part MCD-00074, "Test Point 1mm", Manufacturer=n/a
TP8 TP2000: library part MCD-00713, "Vero Technologies 1.02mm Black Terminal Post", Manufacturer=VERO, Manufacturer_Part_Number=20-2137
TP33: library part MCD-00074, "Test Point 1mm", Manufacturer=N/A
TP34 TP36 TP37 TP38 TP39: library part MCD-00074, "Test Point 1mm", Manufacturer=N/A, Manufacturer_Part_Number=n/a
U1: library part MCD-03375, "MPU , 2xCortex-A35@1.5GHz, Cortex-M33@400MHz, TFBGA 14x14, pitch 0.5, 648KB SRAM, With Crypto", Manufacturer=STMICROELECTRONICS, Package=TFBGA
U2: library part MCD-04160, "Memory, LPDDR4 SDRAM,1V8, 32Gbit, 2133MHz", Manufacturer=MICRON, Package=TFBGA-200
U3 U4 U7 U11 U13 U14 U15 U19 U22 U23 U25 U27 U29 U31 U32 U33 U39 U54: library part MCD-03501, "ESD protection , 0201", Manufacturer=STMICROELECTRONICS, Manufacturer_Part_Number=ESDZL5-1F4, Package=0201
U5 U6 U59 U60: library part MCD-00667, "4-line ESD protection for high speed lines", Manufacturer=STMICROELECTRONICS, Manufacturer_HQ_COO=EU, Package=uQFN-10L
U8 U10 U16 U21 U24: library part MCD-03059, "ESD protection & Common Filter High Speed serial Interfaces , 0.4 pitch", Manufacturer=STMICROELECTRONICS, Package=uQFN-10L
U9: library part MCD-02315, "MIPI/DSI Receiver with HDMI Transmitter", Manufacturer="ANALOG DEVICES", Package="WLCSP-49 pitch 0.5mm"
U12 U53: library part MCD-01715, "MEMS audio sensor omnidirectional digital microphone for industrial applications", Manufacturer=STMICROELECTRONICS, Manufacturer_HQ_COO=EU, Package=HCLGA-4LD
U17 U18 U42 U45 U46: library part MCD-03060, "ESD protection & Common Filter High Speed serial Interfaces , 0.4 pitch", Manufacturer=STMICROELECTRONICS, Package=uQFN-6
U20: library part MCD-02316, "5-line HDMI control line ESD protection", Manufacturer=STMICROELECTRONICS, Package="Flip Chip 9 bumps 0.4 mm pitch"
U26: library part MCD-03000, "STPMIC2", Manufacturer=STMICROELECTRONICS, Package=VQFN
U28: library part MCD-00170, "ESD protection 6V1", Manufacturer=STMICROELECTRONICS, Manufacturer_HQ_COO=EU, Manufacturer_Part_Number=ESDALC6V1-1U2
U34: library part MCD-02348, "2xPort USB 2.0 Hi-Speed Hub Controller", Alternate_Manufacturer=N/A, Manufacturer=MICROCHIP, Package=24-SQFN
U35: library part MCD-02514, "LDO, 3.3V, 300mA, High input voltage: 2.5V to 28V, SOT23-5L", Manufacturer=STMICROELECTRONICS, Package=SOT23-5L
U36: library part MCD-03851, "MCU, ARM Cortex-M7 32-bit, 512KB Flash, 276KB RAM, With Crypto", Manufacturer=STMICROELECTRONICS, Manufacturer_Part_Number=STM32F723IEK6, Package=BGA-176
U37: library part MCD-04155, "Memory, eMMC, 3V3, 8Gbit, 52MHz , V5.1", Manufacturer=KIOXIA, Manufacturer_Part_Number=THGBMUG6C1LBAIL, Package=WFBGA153
U38: library part MCD-01130, "10/100/1000M GIGABIT Ethernet Transceiver, QFN40 , SMPS version", Manufacturer=REALTEK
U40: library part MCD-03465, "IC, IEEE802.11b/g/n W-LAN + Bluetooth 5.2(BR/EDR/BLE) module", Manufacturer=MURATA
U41: library part MCD-00123, "IC,Dual-Channel-Power-Switch,500mA,100mR,SO8", Manufacturer=STMICROELECTRONICS, Manufacturer_HQ_COO=EU
U43 U48: library part MCD-01207, "High power Transient voltage suppressor:25V/35A EOS and ESD transients protection.", Manufacturer=STMICROELECTRONICS, Manufacturer_HQ_COO=EU, Manufacturer_Part_Number=ESDA25P35-1U1M, Package=QFN1610
U44 U51: library part MCD-01026, "High power transient voltage suppressor", Manufacturer=STMICROELECTRONICS, Manufacturer_HQ_COO=EU, Manufacturer_Part_Number=ESDA7P120-1U1M, Package=QFN1610
U47 U57 U58: library part MCD-03060, "IC, ESD protection and Common Filter High Speed serial Interfaces, 10.7 GHz", Manufacturer=STMICROELECTRONICS, Package=uQFN-6
U49: library part MCD-00159, "500mA, Enhanced single channel power switches with active high enable pin", Alternate_Manufacturer="TEXAS INSTRUMENTS", Alternate_Manufacturer_Part_Number=TPS2051C, Manufacturer=STMICROELECTRONICS, Manufacturer_HQ_COO=EU
U50: library part MCD-02130, "USB Type-C Port Protection for USB DRP Power Delivery, PPS compliant", Manufacturer=STMICROELECTRONICS, Manufacturer_HQ_COO=EU, Package=QFN-20L
U52: library part MCD-02532, "IC, eFuse with Fast Overvoltage Protection 2.7V to 18V 4A 34mOhm 8-Pin WSON", Manufacturer="TEXAS INSTRUMENTS", Package=WSON8
U56: library part MCD-02300, "Switch USB3.1 Superspeed 10 Gbps , Gen1 and Gen2", Alternate_Manufacturer=N/A, Manufacturer="ON SEMICONDUCTOR", Package=QFN
X1: library part MCD-01479, "Crystal, 32.768kHz, 6pF, +/-20ppm, 80K, 2.05x1.2mm", Manufacturer=NDK, Manufacturer_Part_Number=NX2012SA-32.768KHZ-EXS00A-MU00527, Package=2.05x1.2mm
X2: library part MCD-02344, "Crystal, 40MHz, 6pF, +/-20ppm, 80R, 1.6x1.2mm", Manufacturer=NDK, Manufacturer_Part_Number=NX1612SA-40MHZ-EXS00A-CS13836, Package=1.6x1.2mm
X3: library part MCD-01036, "Crystal 24MHz, 6pF, +-20ppm, 80ohms max, SMD", Alternate_Manufacturer=N/A, Manufacturer=NDK, Manufacturer_Part_Number=NX2016SA-24MHZ-EXS00A-CS10820, Package=2x1.6mm
X4: library part MCD-01463, "Crystal 25Mhz, 10pF, -+50PPM, SMD", Manufacturer=NDK, Manufacturer_Part_Number=NX3225GA-25MHZ-EXS00A-CG06750, Package=3.2x2.5mm
X6: library part MCD-01627, "Oscillator, SPXO, 24MHz, +/-50ppm, square wave, 3V3, 2x1.6mm", Manufacturer=NDK, Manufacturer_Part_Number=NZ2016SH-24MHZ-END4869F, Package=2x1.6mm
X7: library part MCD-01036, "Crystal, 24MHz, 6pF, +/-20ppm, 80R, 2x1.6mm", Manufacturer=NDK, Manufacturer_Part_Number=NX2016SA-24MHZ-EXS00A-CS10820, Package=2x1.6mm

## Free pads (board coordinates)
  round 6 hole 3.5: 1(3.55,76.05) 1(3.55,4) 1(96,4)
  round 3 hole 2.2 paste-2539.97 mask+0.05: 1(9,76.05) 1(32,76.05)
  round 3.5 hole 3.5 unplated: 1(96,62)

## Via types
v1: diameter 0.55, hole 0.35, Top Layer to Bottom Layer, 823 vias
v2: diameter 0.4, hole 0.2, Top Layer to Bottom Layer, 235 vias
v3: diameter 0.4, hole 0.2, Top Layer to Bottom Layer, tented both sides, 216 vias
v4: diameter 0.5, hole 0.2, Top Layer to Bottom Layer, 159 vias
v5: diameter 0.25/0.3 (per signal layer), hole 0.1, Top Layer to Signal Layer 1, tented both sides, 29 vias

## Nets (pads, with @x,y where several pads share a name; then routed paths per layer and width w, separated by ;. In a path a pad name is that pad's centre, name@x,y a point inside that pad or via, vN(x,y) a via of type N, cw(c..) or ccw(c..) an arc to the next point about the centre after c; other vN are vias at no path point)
1V0_AVDD_RGMII: C302.2 C306.2 C322.2 C323.2 R310.1 U38.3 U38.8 U38.38 | length 20.5
  Top Layer w0.2: v1(38.675,24.65) U38.38@39.45,24.65 ; v1(40.9,22.425) U38.3@40.9,23.2 ; v1(42.9,22.425) U38.8@42.9,23.2
  Signal Layer 2 w0.5: v1(38.675,24.65) 39.45,24.65 40.125,23.975 40.125,23.2 v1(40.9,22.425) v1(42.9,22.425)
  Bottom Layer w0.2: v1(40.9,22.425) 40.9,22.625 C322.2@41.3,23.025 ; C323.2@42.5,23.025 42.9,22.625 v1(42.9,22.425)
  Bottom Layer w0.3: C302.2@38.431,26.144 C302.2@38.45,26.125 38.45,24.943 38.675,24.718 v1(38.675,24.65) 38.723,24.698 38.948,24.698 39.17,24.92 39.195,24.92 39.3,25.025 C306.2@39.3,25.05
  Bottom Layer w0.5: C302.2@38.431,26.144 37.625,26.144 36.85,26.919 36.85,30.325 38.5,31.975 R310.1@39.475,31.975
1V0_DVDD_RGMII: C288.2 C295.2 R313.1 U38.21 | length 3.9
  Top Layer w0.2: U38.21@43.7,28.1 43.7,28.25 44.3,28.25 v1(44.325,28.275)
  Bottom Layer w0.3: R313.1@42.75,29.9 42.75,29.125 C288.2@42.575,28.95 42.7,28.95 43.208,28.442 43.608,28.442 C295.2@43.65,28.4 ; C295.2@43.627,28.423 43.727,28.323 44.277,28.323 v1(44.325,28.275)
1V0_RGMII: C120.2 C123.2 LE1.2 R310.2 R313.2 | length 6.9
  Top Layer w0.5: LE1.2@38.425,31.975 C123.2@40.65,31.975 C120.2@41.775,31.975 v1(42.75,31.975)
  Bottom Layer w0.3: R313.2@42.75,31.3 v1(42.75,31.975)
  Bottom Layer w0.5: R310.2@40.875,31.975 v1(42.75,31.975)
1V8: C118.2 C128.2 C193.2 C194.2 C198.2 C220.2 C236.2 C237.2 C238.2 C239.2 C240.2 C246.2 C253.2 L1.2 L11.2 L16.2 L17.2 L18.2 L19.2 LNK1.2 R101.2 R103.2 R104.2 R248.2 R267.2 R269.1 U1.1E1 U1.AD22 U1.AE23 U1.D18 U1.E17 U1.F20 U1.G5 U1.G7 U1.G9 U1.G19 U1.H6 U37.C6 U37.M4 U37.N4 U37.P3 U37.P5 | length 36.7
  Top Layer w0.15: U1.G5@58.375,44.825 v3(58.375,44.325) U1.H6@58.875,44.325 ; U1.G7@59.375,44.825 59.387,44.837 59.888,44.837 v3(59.9,44.85) 59.912,44.837 60.362,44.837 U1.G9@60.375,44.825 ; v3(59.875,41.675) U1.1E1@60.125,42.075 ; U1.E17@64.375,45.825 v3(64.35,46.375) ; U1.E17@64.377,45.828 v3(64.35,46.375) ; U1.D18@64.875,46.325 64.425,46.368 v3(64.35,46.375) ; U1.G19@65.375,44.825 65.775,44.707 v3(65.8,44.7) 65.809,44.777 U1.F20@65.875,45.325 ; U1.AD22@66.875,36.325 v3(67.375,36.325) U1.AE23@67.375,35.825 ; U37.P3@80.925,56.155 v2(81.325,56.155)
  Top Layer w0.2: LNK1.2@29.1,52.348 v1(29.1,52.95) ; U37.C6@75.425,57.655 75.602,57.832 75.877,57.832 v1(75.925,57.88) ; U37.M4@79.925,56.655 U37.N4@80.425,56.655 ; U37.P3@80.925,56.155 U37.N4@80.425,56.655 ; U37.P5@80.925,57.155 U37.N4@80.425,56.655
  Top Layer w0.3: v1(37.534,67.016) L11.2@38.327,67.016 ; v1(37.537,64.999) L19.2@38.33,64.999 ; v1(53.214,60.449) L17.2@53.214,61.242 ; v1(53.326,68.089) L18.2@53.326,68.882 ; R269.1@58.956,31.358 58.956,30.722 v1(58.958,30.72)
  Top Layer w0.64: C194.2@28,52.95 v1(29.1,52.95) v1(29.78,52.95)
  Top Layer w0.8: L1.2@25.995,51.175 25.995,52.9 26.045,52.95 C198.2@26.15,52.95
  Top Layer w0.9: C193.2@24.3,52.95 C198.2@26.045,52.95 ; C198.2@26.15,52.95 C194.2@28,52.95
  Bottom Layer w0.2: v1(37.537,64.999) v1@37.551,64.985 ; C220.2@59.609,44.406 59.684,44.481 59.684,44.633 v3(59.9,44.85) ; v3(64.35,46.375) 64.4,46.425 C239.2@64.4,46.837 ; 65.888,44.917 65.913,44.942 C238.2@65.913,45.676 ; R101.2@74.375,56.775 74.425,56.775 74.58,56.93 74.58,57.2 75.08,57.7 75.08,57.725 75.235,57.88 C118.2@75.26,57.88 ; R103.2@80.171,57.961 80.769,57.961 ; R104.2@80.175,55.355 80.69,55.355 80.885,55.55 80.885,55.998 81.061,56.174 ; 81.075,57.136 81.075,57.655 80.769,57.961 ; R248.2@81.107,58.98 80.952,58.825 80.952,58.144 80.769,57.961
  Bottom Layer w0.25: C253.2@67.375,34.925 C246.2@67.375,35.525 v3(67.375,36.325)
  Bottom Layer w0.3: v2@56.264,34.232 56.755,34.723 R267.2@57.323,34.723 ; C237.2@56.696,44.325 C236.2@57.35,44.325 v3(58.375,44.325) 58.375,44.352 58.475,44.452 58.475,44.675 C240.2@58.5,44.7 ; C118.2@75.26,57.88 v1(75.925,57.88) ; 81.061,56.174 80.867,56.368 80.867,56.928 81.075,57.136 81.306,57.136 81.325,57.155 C128.2@82.015,57.155
  Bottom Layer w0.5: v1@37.551,64.985 L16.2@38.45,64.985
  other v2: 56.245,34.213
1V8_FB: LNK1.1 U26.35 | length 5.1
  Top Layer w0.15: U26.35@28.7,46.97 28.7,49.311 28.675,49.336 28.675,51.473 LNK1.1@29.1,51.898
3V3: C31.1 C84.2 C115.2 C116.2 C126.2 C135.2 C136.2 C137.2 C182.2 C203.2 C204.2 C206.2 C207.2 C216.2 C224.2 C228.1 C229.1 C232.1 C334.1 C335.1 CN2.3 CN2.4 CN5.1 CN5.17 CN8.22 D1.1 L7.2 L13.2 L15.2 L21.2 R3.1 R13.1 R52.2 R69.1 R76.1 R89.1 R90.1 R91.1 R92.1 R93.1 R94.2 R95.2 R100.1 R105.2 R136.1 R138.2 R142.2 R144.1 R224.2 R228.2 U12.1 U26.3 U26.53 U34.1 U34.9 U34.18 U40.30 U40.36 U50.2 U53.1 U56.17 X6.4 | length 79.4
  Top Layer w0.1: R3.1@10.574,65.1 v1@11.226,65.1
  Top Layer w0.15: v4(23.41,39.977) 23.762,40.329 23.762,41.465 24.697,42.4 U26.53@25.33,42.4 ; U26.53@25.12,42.369 25.419,42.369 U26.53@25.45,42.4
  Top Layer w0.2: X6.4@54.113,64.395 C182.2@55.196,64.395 ; R76.1@55.196,65.185 C182.2@55.196,64.395 ; v1@55.846,64.395 C182.2@55.196,64.395 ; v1(67.757,19.789) 68.297,19.789 68.337,19.829 U34.1@68.337,20.006 ; v1(68.125,24.55) 68.125,24.455 68.337,24.243 U34.18@68.337,23.771 ; U34.9@71.47,21.638 v1(72.249,21.638) ; R93.1@74.95,66.226 R90.1@75.978,66.226 ; R90.1@75.978,66.229 R92.1@77.025,66.229 ; R92.1@77.025,66.232 79.044,66.232 v1(79.047,66.229) ; v1(82.993,19.723) 83.668,19.723 R228.2@83.668,20.723 ; v1(92.118,28.515) C232.1@92.118,29.19 92.81,29.19 94.083,27.917 95.997,27.917 CN5.17@97.27,29.19
  Top Layer w0.21: 26.473,39.598 26.7,39.825 U26.3@26.7,40.63
  Top Layer w0.25: v1(4.135,64.75) CN2.3@5,64.75 ; CN2.4@5,64.25 v1(5.865,64.25) ; v1(68.125,24.55) 68.125,26.153 68.271,26.3 68.733,26.3 R52.2@68.82,26.387 R100.1@69.837,26.387 R95.2@70.844,26.387 R94.2@71.85,26.387 ; U40.30@79.725,68.575 79.725,66.128 79.725,66.003 C135.2@79.728,66 ; U40.36@81.3,69.925 82.515,69.925 C137.2@82.84,70.25 v1(83.52,70.25) ; R69.1@84.416,66.631 v1(84.416,67.259) ; U53.1@87.925,54.52 88.2,54.52 88.875,55.195 C229.1@88.875,56.231 v1(88.875,56.886) ; U12.1@87.925,64.52 88.2,64.52 88.875,65.195 C228.1@88.875,66.231 v1(88.875,66.886)
  Top Layer w0.3: v1(1.841,8.327) R136.1@2.486,8.327 ; v1(1.841,16.327) R142.2@2.486,16.327 ; v1(1.841,24.294) R138.2@2.486,24.294 ; v1(1.841,32.361) R144.1@2.486,32.361 ; C216.2@25.475,37.175 C216.2@25.5,37.175 v4@26.085,37.175 ; CN8.22@26.25,73.222 26.25,72.799 26.426,72.623 27.377,72.623 27.895,72.105 27.92,72.105 28.025,72 v1@28.025,71.325 ; v1(39.302,69.456) L13.2@40.095,69.456 ; C136.2@78.132,65.231 78.685,65.231 v1(79.047,65.593) ; v1(79.047,66.229) v1@79.052,66.224 ; v1(88.113,17.097) U50.2@88.113,17.873
  Top Layer w0.4: C216.2@25.5,37.175 25.514,37.189 25.514,37.685 25.96,38.131 25.96,39.085 26.473,39.598 ; v1@79.052,65.593 v1@79.052,66.224 ; v1@79.057,66.22 C135.2@79.557,66.22
  Top Layer w0.5: v1(36.415,34.17) L21.2@37.27,34.17 ; v1@79.052,66.224 v1@79.057,66.22 ; C135.2@79.557,66.22 79.581,66.195 79.658,66.195 79.725,66.128 79.728,66.125 C135.2@79.728,66
  Top Layer w0.9: C206.2@13.587,38.323 C203.2@19,38.323 20.362,38.323 L7.2@20.387,38.298
  Bottom Layer w0.2: R13.1@51.376,64.947 53.561,64.947 54.108,64.4 v1(55.851,64.4) ; v1(67.757,19.789) C116.2@67.757,20.405 ; C115.2@68.021,23.788 68.125,23.893 v1(68.125,24.55) ; C126.2@71.552,21.638 v1(72.249,21.638) ; v1(79.263,11.31) 79.265,11.313 79.265,12.036 C31.1@79.268,12.039 U56.17@79.268,13.096 ; R105.2@79.854,19.165 v1(79.854,19.84)
  Bottom Layer w0.25: v1(4.135,64.75) C84.2@4.979,64.75 5.069,64.66 5.455,64.66 v1(5.865,64.25) ; v1@39.3,69.458 v1(39.302,69.456)
  Bottom Layer w0.3: D1.1@38.25,69.458 v1@39.3,69.458 ; L15.2@46.77,21.5 v1(47.675,21.5) ; R89.1@78.164,65.734 78.202,65.696 78.876,65.696 78.979,65.593 v1(79.047,65.593) ; v1(79.047,66.229) 79.06,66.242 R91.1@80.045,66.242 ; C334.1@87.413,17.097 v1(88.113,17.097) C335.1@88.813,17.097
  other v1: 13.187,36.823 13.912,36.823 14.637,36.823 13.187,37.498 13.912,37.498 14.637,37.498 11.231,65.095 28.03,71.32
  other v4: 26.11,37.175
3V3_AVDD_RGMII: C309.2 C314.2 C317.2 C332.2 L15.1 U38.11 U38.40 | length 12.4
  Top Layer w0.2: v1(39.25,23.4) 39.25,23.85 U38.40@39.45,23.85 ; U38.11@44.35,23.85 44.55,23.85 v1(44.55,23.4)
  Bottom Layer w0.2: v1(39.25,23.4) 39.317,23.333 39.832,23.333 C309.2@39.945,23.22 ; C317.2@43.75,23.15 44.3,23.15 v1(44.55,23.4) C314.2@44.55,24.1
  Bottom Layer w0.3: C309.2@39.945,23.22 39.945,22.355 40.525,21.775 43.75,21.775 ; C317.2@43.75,23.15 43.75,21.775 ; L15.1@45.17,21.5 44.52,20.85 C332.2@44.025,20.85 44.025,21.5 43.75,21.775
3V3_DVDD_RGMII: C103.2 C104.2 C109.2 C111.2 C141.2 C280.1 C296.2 L21.1 R109.2 R110.2 R111.2 R112.2 R114.2 R191.2 R195.2 R233.2 R318.2 R319.1 U38.28 U38.29 | length 44.2
  Top Layer w0.2: U38.29@40.5,28.1 40.5,28.675 v1(40.7,28.875) 40.9,28.675 U38.28@40.9,28.1
  Top Layer w0.3: R233.2@31.44,9.186 v1(31.44,9.861)
  Top Layer w0.5: L21.1@38.87,34.17 v1(39.725,34.17) C111.2@40.42,34.17
  Signal Layer 3 w0.3: v1(31.44,9.861) 31.44,10.615 33.425,12.6 33.425,18.351 34.587,19.514 34.587,24.437 36.562,26.411 36.562,27.98 37.621,29.039 40.469,29.039 40.632,28.875 v1(40.7,28.875)
  Bottom Layer w0.2: R319.1@37.625,29.725 R318.2@38.65,29.725 39.63,29.725 39.825,29.53 C280.1@39.825,29 ; C104.2@43.675,33.626 v1(44.346,33.625) ; v1(44.346,33.625) R109.2@44.97,33.625 ; C141.2@49.41,28.065 v1(48.74,28.065) 48.07,28.065 R112.2@48.07,29.53 R111.2@48.07,30.545 R110.2@48.07,31.565 v1(48.74,31.565) C103.2@49.409,31.565
  Bottom Layer w0.25: R195.2@47.27,23.8 47.755,23.8 47.945,23.99 v1(47.945,24.8) 47.997,24.748 48.312,24.748 48.459,24.602 48.459,24.375 48.589,24.245 C109.2@48.614,24.245
  Bottom Layer w0.3: C280.1@39.825,29 39.902,28.923 40.652,28.923 v1(40.7,28.875) 40.7,28.85 C296.2@41.3,28.25 ; R191.2@47.27,24.8 v1(47.945,24.8)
